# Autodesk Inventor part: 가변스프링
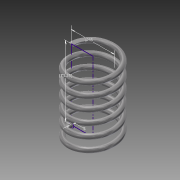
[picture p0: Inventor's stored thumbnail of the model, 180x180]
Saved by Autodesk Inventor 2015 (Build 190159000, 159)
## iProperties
Created: 2015-10
Part Number: 가변스프링
Material: Steel, Mild
Document SubType Name: Modeling
Designer: youjin21
Density: 7.85 g/cm^3
Appearance: Semi-Polished
Mass: 128.854 g
Surface Area: 132.996 cm^2
Volume: 16.4145 cm^3
Author: youjin21
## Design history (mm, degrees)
sketch "Sketch1"
  geometry: L1 (22.5, 73.25)-(0, 73.25); L2 (0, 73.25)-(0, 0); L3 (0, 0)-(22.5, 0); L4 (22.5, 0)-(22.5, 73.25); C1 r 2.5 at (22.5, 0); 1 further point
  constraints: 8 end point, 2 coincident, 2 parallel, 1 centre point, 1 horizontal, 1 perpendicular
  dimensions: "d0" = 73.25 distance between parallel lines of L3 L1 (derived); "d1" = 45 diameter of L4 L2; "d2" = 5 diameter of C1
coil "Coil1" pitch "d3" = 10; turns "d5" = 6; dims "d4" = 73.25 (= d0), "d6" = 0, angle "d7" = 90 deg, angle "d8" = 90 deg, "d9" = 0, "d10" = 0
sketch "Sketch2"
  geometry: L1 (-25, 0)-(-20, 0) reference; 1 further point
  constraints: 1 horizontal alignment
extrude "Extrusion1" cut sketch "Sketch2" stored distance "d11" = 10; taper "d12" = 0 deg
workplane "Work Plane1"
sketch "Sketch3"
  geometry: L1 (25, 0)-(20, 0) reference; 1 further point
  constraints: 1 horizontal alignment
extrude "Extrusion2" cut sketch "Sketch3" stored distance "d13" = 10; taper "d14" = 0 deg
body "Solid1"
node "Project Cut Edges1"
node "Project Cut Edges2"
